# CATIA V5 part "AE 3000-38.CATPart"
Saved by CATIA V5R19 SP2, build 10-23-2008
Part number: AE 3000-38
Bounding box of the stored display mesh (mm): x -47.487 to 47.487, y -47.487 to 47.487, z 0 to 146
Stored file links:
  C:\Users\Bora\Desktop\3D Katı model\AE serisi\AE 3000\AE 3000-38.CATPart
  C:\Program Files\Dassault Systemes\B19\intel_a\reffiles\standard\MetricThickPitch.txt
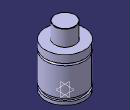
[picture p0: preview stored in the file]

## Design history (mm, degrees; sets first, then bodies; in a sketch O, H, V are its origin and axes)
Body1 (main body)
  Sketch1 on yz-plane, origin (0, 0, 0), H (0, 1, 0), V (0, 0, 1)
    point P1 (47.5, 88.5)
    point P5 (25, 145)
    point P7 (25, 145)
    point P12 (47.5, 83.5)
    point P13 (47.5, 88.5)
    point P14 (47.5, 83.5)
    line L1 (47.5, 88.5) -> (47.5, 107)
    line L2 (47.5, 0) -> (47.5, 8)
    arc A1 centre (24, 145) radius 1 from (25, 145) to (24, 146) ccw
    line L3 (25, 145) -> (25, 107)
    line L4 (43.5, 15) -> (43.5, 8)
    line L5 (47.5, 15) -> (47.5, 83.5)
    arc A2 centre (47.5, 86) radius 2.5 from (47.5, 88.5) to (47.5, 83.5) ccw
    line L6 (24, 146) -> (0, 146)
    point P15 (0, 146)
    line L7 (25, 107) -> (47.5, 107)
    line L8 (0, 0) -> (47.5, 0)
    line L9 (43.5, 15) -> (47.5, 15)
    line L10 (43.5, 8) -> (47.5, 8)
    coincidence: P15 V, P1 P13, P5 P7, P12 P14
    tangency: L6 A1
    horizontal: L7 H, L8 H, L9 H, L10 H
  Shaft1: profile Sketch1, axis Sketch1.V, angle 360
  Sketch2 on face of Shaft1 from Sketch1.L8, origin (0, 0, 0), H (1, 0, 0), V (0, -1, 0)
    point P1 (30, 0)
    distance P1 V = 30
  Hole1: placed by Sketch2, at (30, 0, 0) direction (0, 0, 1), diameter 6.647, depth 13, threaded "M8", thread diameter 8, thread depth 13, pitch 1.25
  CircPattern1: of Hole1, instances 4, angular step 90, axis from xy-plane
